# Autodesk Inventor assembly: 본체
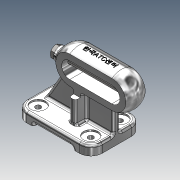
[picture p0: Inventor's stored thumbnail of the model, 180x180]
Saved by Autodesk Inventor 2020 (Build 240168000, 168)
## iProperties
Created: 2025-01
Part Number: 본체
Document SubType Name: Assembly
Designer: 1강의실14
Author: 1강의실14
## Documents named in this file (3)
- C:\Users\1강의실14\Desktop\750103V1002\본체.iam
- C:\Users\1강의실14\Desktop\750103V1002\본체.ipt
- C:\Users\1강의실14\Desktop\750103V1002\육각 머리 볼트 M8x80.ipt
